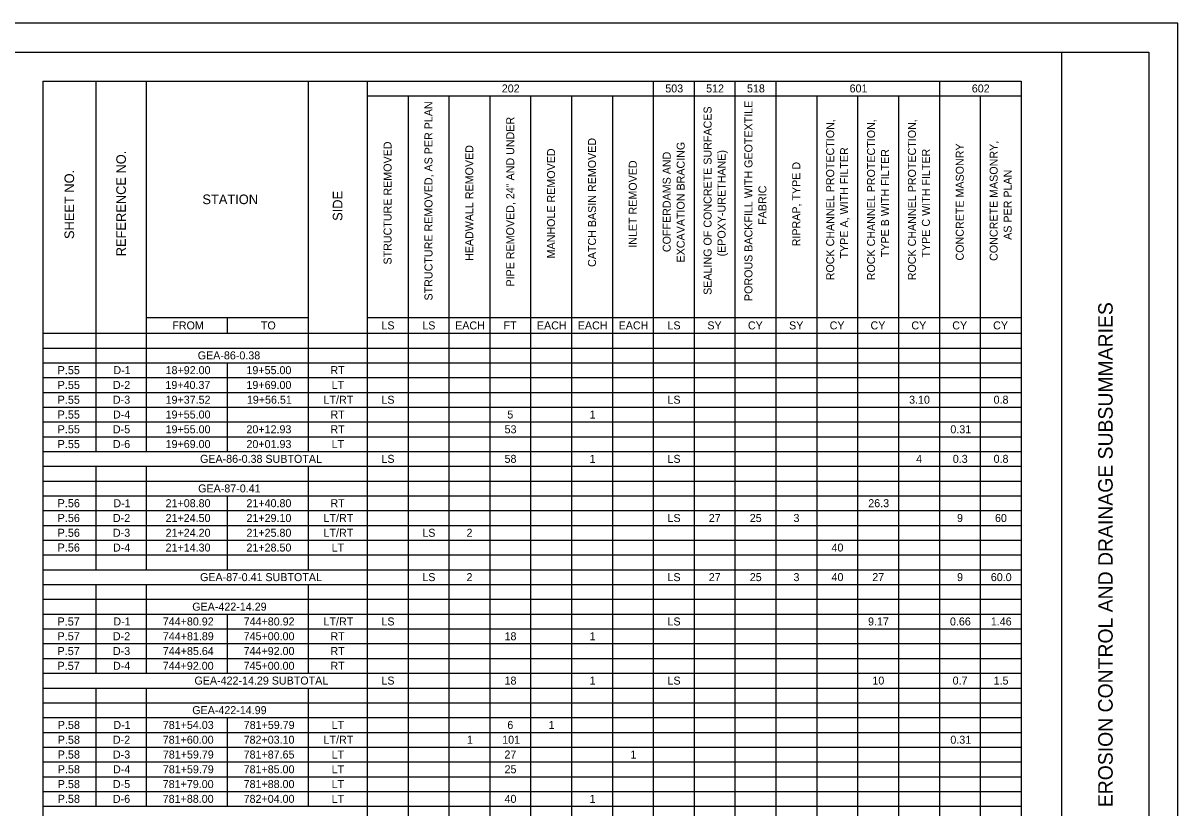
# Model space of a CAD drawing. Extents: x 0 to 34, y 0 to 22.
# Drawn here: x 14.08 to 34, y 8.46 to 22 of the extents above; entities that cross this region are included whole.
import ezdxf

# ---------------------------------------------------------------- set-up
doc = ezdxf.new("R2010")
doc.units = 0
for name, color, linetype in [('SH_Border', 7, 'Continuous'), ('SH_Cut_Line', 7, 'Continuous'), ('SH_Data', 7, 'Continuous'), ('SH_Text', 7, 'Continuous')]:
    doc.layers.add(name, color=color, linetype=linetype)

msp = doc.modelspace()

# ---------------------------------------------------------------- linework, layer by layer
at = {"layer": 'SH_Border'}
msp.add_line((32, 0.5), (32, 21.5), dxfattribs=at)
msp.add_lwpolyline([(1.5, 21.5), (33.5, 21.5), (33.5, 0.5), (1.5, 0.5)], close=True, dxfattribs=at)
at = {"layer": 'SH_Cut_Line'}
msp.add_lwpolyline([(0, 0), (34, 0), (34, 22), (0, 22)], close=True, dxfattribs=at)
at = {"layer": 'SH_Text'}
for p, q in [((14.42, 21), (31.295, 21)), ((14.42, 21), (14.42, 2.625)), ((15.335, 21), (15.335, 14.61)), ((16.205, 21), (16.205, 14.61)), ((18.995, 21), (18.995, 14.61)), ((20.015, 21), (20.015, 2.625)), ((24.95, 21), (24.95, 2.625)), ((25.655, 21), (25.655, 2.625)), ((26.36, 21), (26.36, 2.625)), ((27.065, 21), (27.065, 2.625)), ((29.885, 21), (29.885, 2.625)), ((31.295, 21), (31.295, 2.625)), ((20.015, 20.745), (31.295, 20.745)), ((20.72, 20.745), (20.72, 2.625)), ((21.425, 20.745), (21.425, 2.625)), ((22.13, 20.745), (22.13, 2.625)), ((22.835, 20.745), (22.835, 2.625)), ((23.54, 20.745), (23.54, 2.625)), ((24.245, 20.745), (24.245, 2.625)), ((27.77, 20.745), (27.77, 2.625)), ((28.475, 20.745), (28.475, 2.625)), ((29.18, 20.745), (29.18, 2.625)), ((30.59, 20.745), (30.59, 2.625)), ((16.205, 16.92), (18.995, 16.92)), ((17.6, 16.92), (17.6, 16.65)), ((20.015, 16.92), (31.295, 16.92)), ((14.42, 16.65), (31.295, 16.65)), ((14.42, 16.395), (31.295, 16.395)), ((14.42, 16.14), (31.295, 16.14)), ((17.6, 16.14), (17.6, 14.61)), ((14.42, 15.885), (31.295, 15.885)), ((14.42, 15.63), (31.295, 15.63)), ((14.42, 15.375), (31.295, 15.375)), ((14.42, 15.12), (31.295, 15.12)), ((14.42, 14.865), (31.295, 14.865)), ((14.42, 14.61), (31.295, 14.61)), ((14.42, 14.355), (31.295, 14.355)), ((15.335, 14.355), (15.335, 12.57)), ((16.205, 14.355), (16.205, 12.57)), ((18.995, 14.355), (18.995, 12.57)), ((14.42, 14.1), (31.295, 14.1)), ((14.42, 13.845), (31.295, 13.845)), ((17.6, 13.845), (17.6, 12.57)), ((14.42, 13.59), (31.295, 13.59)), ((14.42, 13.335), (31.295, 13.335)), ((14.42, 13.08), (31.295, 13.08)), ((14.42, 12.825), (31.295, 12.825)), ((14.42, 12.57), (31.295, 12.57)), ((14.42, 12.315), (31.295, 12.315)), ((15.335, 12.315), (15.335, 10.785)), ((16.205, 12.315), (16.205, 10.785)), ((18.995, 12.315), (18.995, 10.785)), ((14.42, 12.06), (31.295, 12.06)), ((14.42, 11.805), (31.295, 11.805)), ((17.6, 11.805), (17.6, 10.785)), ((14.42, 11.55), (31.295, 11.55)), ((14.42, 11.295), (31.295, 11.295)), ((14.42, 11.04), (31.295, 11.04)), ((14.42, 10.785), (31.295, 10.785)), ((14.42, 10.53), (31.295, 10.53)), ((15.335, 10.53), (15.335, 8.49)), ((16.205, 10.53), (16.205, 8.49)), ((18.995, 10.53), (18.995, 8.49)), ((14.42, 10.275), (31.295, 10.275)), ((14.42, 10.02), (31.295, 10.02)), ((17.6, 10.02), (17.6, 8.49)), ((14.42, 9.765), (31.295, 9.765)), ((14.42, 9.51), (31.295, 9.51)), ((14.42, 9.255), (31.295, 9.255)), ((14.42, 9), (31.295, 9)), ((14.42, 8.745), (31.295, 8.745)), ((14.42, 8.49), (31.295, 8.49))]:
    msp.add_line(p, q, dxfattribs=at)

# ---------------------------------------------------------------- texts
at = {"layer": 'SH_Data'}
msp.add_text('EROSION CONTROL AND DRAINAGE SUBSUMMARIES', height=0.25, rotation=90, dxfattribs=at).set_placement((32.875, 8.474))
at = {"layer": 'SH_Text'}
for s, height, p in [('202', 0.138, (22.337, 20.804)), ('503', 0.138, (25.158, 20.804)), ('512', 0.138, (25.862, 20.804)), ('518', 0.138, (26.567, 20.804)), ('601', 0.138, (28.337, 20.804)), ('602', 0.138, (30.445, 20.804)), ('STATION', 0.1656, (17.173, 18.877)), ('FROM', 0.138, (16.654, 16.716)), ('TO', 0.138, (18.182, 16.716)), ('LS', 0.138, (20.261, 16.716)), ('LS', 0.138, (20.966, 16.716)), ('EACH', 0.138, (21.533, 16.716)), ('FT', 0.138, (22.368, 16.716)), ('EACH', 0.138, (22.943, 16.716)), ('EACH', 0.138, (23.648, 16.716)), ('EACH', 0.138, (24.353, 16.716)), ('LS', 0.138, (25.196, 16.716)), ('SY', 0.138, (25.883, 16.716)), ('CY', 0.138, (26.583, 16.716)), ('SY', 0.138, (27.293, 16.716)), ('CY', 0.138, (27.993, 16.716)), ('CY', 0.138, (28.698, 16.716)), ('CY', 0.138, (29.403, 16.716)), ('CY', 0.138, (30.108, 16.716)), ('CY', 0.138, (30.813, 16.716)), ('GEA-86-0.38', 0.138, (17.093, 16.199)), ('P.55', 0.14, (14.675, 15.943)), ('D-1', 0.138, (15.637, 15.944)), ('18+92.00', 0.138, (16.538, 15.944)), ('19+55.00', 0.138, (17.933, 15.944)), ('RT', 0.138, (19.382, 15.944)), ('P.55', 0.14, (14.675, 15.688)), ('D-2', 0.138, (15.63, 15.689)), ('19+40.37', 0.138, (16.535, 15.689)), ('19+69.00', 0.138, (17.933, 15.689)), ('LT', 0.138, (19.402, 15.689)), ('P.55', 0.14, (14.675, 15.433)), ('D-3', 0.138, (15.63, 15.434)), ('19+37.52', 0.138, (16.538, 15.434)), ('19+56.51', 0.138, (17.94, 15.434)), ('LT/RT', 0.138, (19.263, 15.434)), ('LS', 0.138, (20.261, 15.434)), ('LS', 0.138, (25.196, 15.434)), ('3.10', 0.138, (29.363, 15.434)), ('0.8', 0.138, (30.821, 15.434)), ('P.55', 0.14, (14.675, 15.178)), ('D-4', 0.138, (15.631, 15.179)), ('19+55.00', 0.138, (16.538, 15.179)), ('RT', 0.138, (19.382, 15.179)), ('5', 0.138, (22.433, 15.179)), ('1', 0.138, (23.851, 15.179)), ('P.55', 0.14, (14.675, 14.923)), ('D-5', 0.138, (15.629, 14.924)), ('19+55.00', 0.138, (16.538, 14.924)), ('20+12.93', 0.138, (17.933, 14.924)), ('RT', 0.138, (19.382, 14.924)), ('53', 0.138, (22.386, 14.924)), ('0.31', 0.138, (30.075, 14.924)), ('P.55', 0.14, (14.675, 14.668)), ('D-6', 0.138, (15.629, 14.669)), ('19+69.00', 0.138, (16.538, 14.669)), ('20+01.93', 0.138, (17.933, 14.669)), ('LT', 0.138, (19.402, 14.669)), ('GEA-86-0.38 SUBTOTAL', 0.138, (17.132, 14.414)), ('LS', 0.138, (20.261, 14.414)), ('58', 0.138, (22.385, 14.414)), ('1', 0.138, (23.851, 14.414)), ('LS', 0.138, (25.196, 14.414)), ('4', 0.138, (29.485, 14.414)), ('0.3', 0.138, (30.117, 14.414)), ('0.8', 0.138, (30.821, 14.414)), ('GEA-87-0.41', 0.138, (17.1, 13.904)), ('P.56', 0.14, (14.675, 13.648)), ('D-1', 0.138, (15.637, 13.649)), ('21+08.80', 0.138, (16.538, 13.649)), ('21+40.80', 0.138, (17.933, 13.649)), ('RT', 0.138, (19.382, 13.649)), ('26.3', 0.138, (28.659, 13.649)), ('P.56', 0.14, (14.675, 13.393)), ('D-2', 0.138, (15.63, 13.394)), ('21+24.50', 0.138, (16.538, 13.394)), ('21+29.10', 0.138, (17.933, 13.394)), ('LT/RT', 0.138, (19.263, 13.394)), ('LS', 0.138, (25.196, 13.394)), ('27', 0.138, (25.908, 13.394)), ('25', 0.138, (26.615, 13.394)), ('3', 0.138, (27.369, 13.394)), ('9', 0.138, (30.19, 13.394)), ('60', 0.138, (30.845, 13.394)), ('P.56', 0.14, (14.675, 13.138)), ('D-3', 0.138, (15.63, 13.139)), ('21+24.20', 0.138, (16.538, 13.139)), ('21+25.80', 0.138, (17.933, 13.139)), ('LT/RT', 0.138, (19.263, 13.139)), ('LS', 0.138, (20.966, 13.139)), ('2', 0.138, (21.729, 13.139)), ('P.56', 0.14, (14.675, 12.883)), ('D-4', 0.138, (15.631, 12.884)), ('21+14.30', 0.138, (16.538, 12.884)), ('21+28.50', 0.138, (17.933, 12.884)), ('LT', 0.138, (19.402, 12.884)), ('40', 0.138, (28.025, 12.884)), ('GEA-87-0.41 SUBTOTAL', 0.138, (17.132, 12.374)), ('LS', 0.138, (20.966, 12.374)), ('2', 0.138, (21.729, 12.374)), ('LS', 0.138, (25.196, 12.374)), ('27', 0.138, (25.908, 12.374)), ('25', 0.138, (26.615, 12.374)), ('3', 0.138, (27.369, 12.374)), ('40', 0.138, (28.025, 12.374)), ('27', 0.138, (28.728, 12.374)), ('9', 0.138, (30.19, 12.374)), ('60.0', 0.138, (30.773, 12.374)), ('GEA-422-14.29', 0.138, (16.998, 11.864)), ('LT/RT', 0.138, (19.263, 11.609)), ('P.57', 0.14, (14.673, 11.608)), ('D-1', 0.138, (15.637, 11.609)), ('744+80.92', 0.138, (16.49, 11.609)), ('744+80.92', 0.138, (17.885, 11.609)), ('LS', 0.138, (20.261, 11.609)), ('LS', 0.138, (25.196, 11.609)), ('9.17', 0.138, (28.655, 11.609)), ('0.66', 0.138, (30.068, 11.609)), ('1.46', 0.138, (30.773, 11.609)), ('P.57', 0.14, (14.673, 11.353)), ('D-2', 0.138, (15.63, 11.354)), ('744+81.89', 0.138, (16.491, 11.354)), ('745+00.00', 0.138, (17.884, 11.354)), ('RT', 0.138, (19.382, 11.354)), ('18', 0.138, (22.385, 11.354)), ('1', 0.138, (23.851, 11.354)), ('P.57', 0.14, (14.673, 11.098)), ('D-3', 0.138, (15.63, 11.099)), ('744+85.64', 0.138, (16.491, 11.099)), ('744+92.00', 0.138, (17.884, 11.099)), ('RT', 0.138, (19.382, 11.099)), ('P.57', 0.14, (14.673, 10.843)), ('D-4', 0.138, (15.631, 10.844)), ('744+92.00', 0.138, (16.489, 10.844)), ('745+00.00', 0.138, (17.884, 10.844)), ('RT', 0.138, (19.382, 10.844)), ('GEA-422-14.29 SUBTOTAL', 0.138, (17.036, 10.589)), ('LS', 0.138, (20.261, 10.589)), ('18', 0.138, (22.385, 10.589)), ('1', 0.138, (23.851, 10.589)), ('LS', 0.138, (25.196, 10.589)), ('10', 0.138, (28.73, 10.589)), ('0.7', 0.138, (30.114, 10.589)), ('1.5', 0.138, (30.821, 10.589)), ('GEA-422-14.99', 0.138, (16.998, 10.079)), ('P.58', 0.14, (14.676, 9.823)), ('D-1', 0.138, (15.637, 9.824)), ('781+54.03', 0.138, (16.49, 9.824)), ('781+59.79', 0.138, (17.886, 9.824)), ('LT', 0.138, (19.402, 9.824)), ('6', 0.138, (22.433, 9.824)), ('1', 0.138, (23.146, 9.824)), ('P.58', 0.14, (14.676, 9.568)), ('D-2', 0.138, (15.63, 9.569)), ('781+60.00', 0.138, (16.489, 9.569)), ('782+03.10', 0.138, (17.884, 9.569)), ('LT/RT', 0.138, (19.263, 9.569)), ('1', 0.138, (21.736, 9.569)), ('101', 0.138, (22.344, 9.569)), ('0.31', 0.138, (30.075, 9.569)), ('P.58', 0.14, (14.676, 9.313)), ('D-3', 0.138, (15.63, 9.314)), ('781+59.79', 0.138, (16.491, 9.314)), ('781+87.65', 0.138, (17.884, 9.314)), ('LT', 0.138, (19.402, 9.314)), ('27', 0.138, (22.383, 9.314)), ('1', 0.138, (24.556, 9.314)), ('P.58', 0.14, (14.676, 9.058)), ('D-4', 0.138, (15.631, 9.059)), ('781+59.79', 0.138, (16.491, 9.059)), ('781+85.00', 0.138, (17.884, 9.059)), ('LT', 0.138, (19.402, 9.059)), ('25', 0.138, (22.385, 9.059)), ('P.58', 0.14, (14.676, 8.803)), ('D-5', 0.138, (15.629, 8.804)), ('781+79.00', 0.138, (16.489, 8.804)), ('781+88.00', 0.138, (17.884, 8.804)), ('LT', 0.138, (19.402, 8.804)), ('P.58', 0.14, (14.676, 8.548)), ('D-6', 0.138, (15.629, 8.549)), ('781+88.00', 0.138, (16.489, 8.549)), ('782+04.00', 0.138, (17.884, 8.549)), ('LT', 0.138, (19.402, 8.549)), ('40', 0.138, (22.385, 8.549)), ('1', 0.138, (23.851, 8.549))]:
    msp.add_text(s, height=height, dxfattribs=at).set_placement(p)
for s, height, p in [('STRUCTURE REMOVED, AS PER PLAN', 0.138, (21.142, 17.215)), ('SEALING OF CONCRETE SURFACES ', 0.138, (25.956, 17.312)), ('POROUS BACKFILL WITH GEOTEXTILE ', 0.138, (26.661, 17.205)), ('PIPE REMOVED, 24" AND UNDER', 0.138, (22.552, 17.456)), (' ROCK CHANNEL PROTECTION,', 0.138, (28.071, 17.512)), (' ROCK CHANNEL PROTECTION,', 0.138, (28.776, 17.512)), (' ROCK CHANNEL PROTECTION,', 0.138, (29.481, 17.512)), ('STRUCTURE REMOVED', 0.138, (20.436, 17.835)), ('CATCH BASIN REMOVED', 0.138, (23.962, 17.794)), ('EXCAVATION BRACING', 0.138, (25.492, 17.871)), (' CONCRETE MASONRY,', 0.138, (30.891, 17.847)), ('REFERENCE NO.', 0.1656, (15.853, 17.978)), ('HEADWALL REMOVED', 0.138, (21.846, 17.896)), ('MANHOLE REMOVED', 0.138, (23.256, 17.941)), (' COFFERDAMS AND', 0.138, (25.251, 17.998)), ('(EPOXY-URETHANE)', 0.138, (26.197, 17.975)), ('TYPE A, WITH FILTER', 0.138, (28.312, 17.94)), ('TYPE B WITH FILTER', 0.138, (29.017, 17.961)), ('TYPE C WITH FILTER', 0.138, (29.722, 17.956)), (' CONCRETE MASONRY', 0.138, (30.306, 17.853)), ('INLET REMOVED', 0.138, (24.666, 18.125)), ('RIPRAP, TYPE D', 0.138, (27.486, 18.149)), ('SHEET NO.', 0.1656, (14.96, 18.275)), ('AS PER PLAN', 0.138, (31.132, 18.261)), ('FABRIC', 0.138, (26.902, 18.52)), ('SIDE', 0.1656, (19.588, 18.588))]:
    msp.add_text(s, height=height, rotation=90, dxfattribs=at).set_placement(p)

doc.saveas('drawing.dxf')
